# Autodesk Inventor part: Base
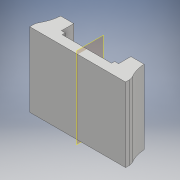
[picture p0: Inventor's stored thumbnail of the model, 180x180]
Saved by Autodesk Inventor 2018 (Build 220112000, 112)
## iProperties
Created: 2022-01
Part Number: Base
Material: Generic
Document SubType Name: Modelado
Designer: Asus
Density: 1 g/cm^3
Appearance: Default
Author: Asus
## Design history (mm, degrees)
sketch "Boceto1"
  geometry: L1 (135, 120)-(-135, 120); L2 (-135, 120)-(-135, -120); L3 (-135, -120)-(135, -120); L4 (135, -120)-(135, 120); L5 (135, 120)-(-135, -120); L6 (-135, 120)-(135, -120); 1 further point
  constraints: 12 end point, 2 midpoint, 2 parallel, 1 horizontal, 1 perpendicular
  dimensions: "d0" = 270 distance of L3.end L2.end; "d1" = 240 distance of L2.end L1.end
extrude "Extrusión1" new body sketch "Boceto1" distance "d2" = 80; taper "d3" = 0 deg
sketch "Boceto2"
  geometry: L1 (0, 120)-(80, 120) reference; L2 (80, 120)-(80, -120) reference; L3 (80, -120)-(0, -120) reference; L4 (0, -120)-(0, 120) reference; L5 (0, 120)-(80, 120) reference; L6 (80, 120)-(80, -120) reference; L7 (80, -120)-(0, -120) reference; L8 (0, -120)-(0, 120) reference; L9 (0, 120)-(80, 120) reference; L10 (80, 120)-(80, -120) reference; L11 (80, -120)-(0, -120) reference; L12 (0, -120)-(0, 120) reference; L13 (0, 120)-(80, 120) reference; L14 (80, 120)-(80, -120) reference; L15 (80, -120)-(0, -120) reference; L16 (0, -120)-(0, 120) reference; L17 (0, 120)-(80, 120) reference; L18 (80, 120)-(80, -120) reference; L19 (80, -120)-(0, -120) reference; L20 (0, -120)-(0, 120) reference; L21 (80, 120)-(30, 120); L22 (0, 120)-(80, 120) reference; L23 (0, -120)-(80, -120) reference; L24 (30, 120)-(80, -120); L25 (80, -120)-(80, 120); 1 further point
  constraints: 6 end point, 1 perpendicular, 1 point on line
  dimensions: "d4" = 50 distance of L1.end L21.end
extrude "Extrusión2" cut sketch "Boceto2" stored distance "d5" = 160; taper "d6" = 0 deg
sketch "Boceto3"
  geometry: L1 (-120, 0)-(-120, 80) reference; L2 (-120, 80)-(-120, 40); L3 (-120, 80)-(0, 80); L4 (120, 80)-(-120, 80) reference; L5 (0, 80)-(0, 20); L6 (0, 20)-(-20, 20); L7 (-20, 20)-(-20, 40); L8 (-20, 40)-(-120, 40); 1 further point
  constraints: 12 end point, 2 midpoint, 2 perpendicular, 1 horizontal
  dimensions: "d8" = 40 distance of L1.end L2.end; "d9" = 120 distance of L1.end L3.end (derived); "d10" = 60 distance of L3.end L5.end; "d11" = 20 distance of L5.end L6.end; "d12" = 20 distance of L6.end L7.end
extrude "Extrusión3" cut sketch "Boceto3" distance "d13" = 12.5; taper "d14" = 0 deg
sketch "Boceto4"
  geometry: L1 (0, 80)-(0, 20); L2 (0, 80)-(120, 80); L3 (120, 80)-(120, 40); L4 (0, 20)-(20, 20); L5 (20, 20)-(20, 40); L6 (20, 40)-(120, 40); 3 further points
  constraints: 12 end point, 1 horizontal, 1 perpendicular
  dimensions: "d16" = 120 distance of point (-120, 80) L1.start (derived); "d17" = 60 distance of L1.start L1.end; "d20" = 20 distance of L1.end L4.end; "d21" = 20 distance of L4.end L5.end
extrude "Extrusión4" cut sketch "Boceto4" distance "d22" = 12.5; taper "d23" = 0 deg
sketch "Boceto5"
  geometry: L1 (0, 0)-(-20, 0); L2 (-20, 0)-(-20, 20); L3 (270, 0)-(270, 80) reference; L4 (270, 80)-(270, 0); L5 (270, 0)-(290, 0); L6 (290, 0)-(290, 20); L7 (270, 0)-(0, 0) reference; L8 (0, 80)-(55, 80) reference; L9 (0, 0)-(0, 80); A1 r 122.729 centre (-122.5, 87.5) between (-20, 20) and (0, 80); A2 r 122.729 centre (392.5, 87.5) between (270, 80) and (290, 20); 1 further point
  constraints: 12 end point, 4 perpendicular, 4 point on circle, 2 centre point, 1 collinear, 1 horizontal
  dimensions: "d24" = 20 distance of L1.start L1.end; "d25" = 20 distance of L1.end L2.end; "d26" = 20 distance of L3.start L5.end; "d27" = 20 distance of L5.end L6.end; "d28" = 122.729 radius of A2
extrude "Extrusión5" join sketch "Boceto5" distance "d29" = 240; taper "d30" = 0 deg
fillet "Empalme1" dims "d31" = 30
node "Sólido1"
node "Proyectar aristas de corte1"
node "Proyectar aristas de corte2"
node "Proyectar aristas de corte3"
node "Proyectar aristas de corte4"
node "Proyectar aristas de corte5"
other parameters: "Grosor" = 0.5, "FactorK" = 4.4, "Radio_pliegue" = 0.5 (= Grosor), "Anchura_desahogo_plegado" = 0.5 (= Grosor), "Profundidad_desahogo_plegado" = 0.25 (= 0.5 x Grosor), "Tamaño_destalonado" = 2 (= 4 x Grosor), "Separación_entre_unión" = 0.01, "Remanente_mínimo" = 1 (= 2 x Grosor), "Radiodetransición" = 0.5 (= Radio_pliegue), "Tamaño_de_radio_de_Jacobi" = 0.5 (= Grosor), "TamañoSeparación" = 0.5 (= Grosor)
